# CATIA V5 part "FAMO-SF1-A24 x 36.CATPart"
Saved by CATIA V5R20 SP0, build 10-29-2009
Part number: FAMO-SF1-A24 x 36
Definition: NONE
Nomenclature: FAMO-SF1-A24 x 36
Source: Unknown
Description: FAMO-SF1-A24 x 36
Bounding box of the stored display mesh (mm): x -13 to 23, y -22 to 22, z -22 to 22
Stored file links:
  C:\Users\Utente\Desktop\IO LAVORO\3D X SITO CF\X SITO\FAMO\FAMO-SF1-A24 x 36.CATPart
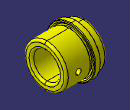
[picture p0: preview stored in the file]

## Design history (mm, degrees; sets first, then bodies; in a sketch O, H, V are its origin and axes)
Body1 "FAMO-SF1-A24 x 36" (main body)
  Solid1: solid without history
